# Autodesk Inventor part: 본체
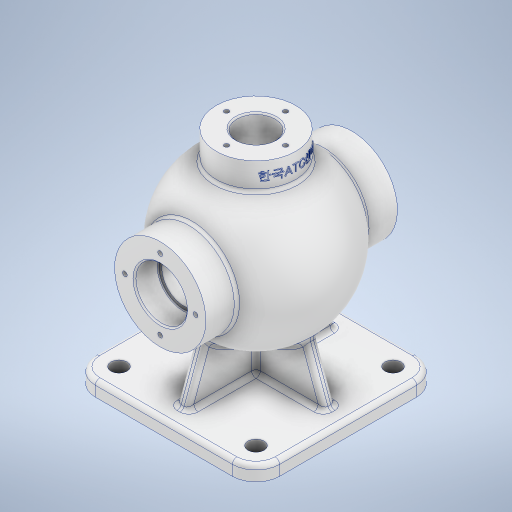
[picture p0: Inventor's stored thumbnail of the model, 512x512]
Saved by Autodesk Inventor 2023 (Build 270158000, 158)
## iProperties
Created: 2023-07
Part Number: 본체
Material: 알루미늄 6061
Document SubType Name: Modeling
Designer: Owner
Density: 2.7 g/cm^3
Appearance: 알루미늄 - 평지
Mass: 1526.65 g
Surface Area: 1174.15 cm^2
Volume: 565.427 cm^3
Author: Owner
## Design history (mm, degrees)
sketch "스케치3"
  geometry: L1 (-62.5, -62.5)-(62.5, -62.5); L2 (62.5, -62.5)-(62.5, 62.5); L3 (62.5, 62.5)-(-62.5, 62.5); L4 (-62.5, 62.5)-(-62.5, -62.5); L5 (-62.5, -62.5)-(62.5, 62.5); L6 (62.5, -62.5)-(-62.5, 62.5); 1 further point
  constraints: 12 end point, 2 midpoint, 2 parallel, 2 perpendicular, 1 horizontal
  dimensions: "d3" = 125 distance of L1.end L2.end
extrude "돌출1" new body sketch "스케치3" distance "d4" = 10; taper "d5" = 0 deg
sketch "스케치6"
  geometry: L1 (0, 62.5)-(0, -62.5) reference; L2 (85, 65)-(54, 65); L3 (54, -65)-(85, -65); L4 (85, -65)-(85, 65); L5 (85, 65)-(85, 54); L6 (85, -54)-(85, -65); L7 (54, 65)-(54, 44.215); L8 (54, -44.215)-(54, -65); L9 (85, 54)-(85, -54); A1 r 54 centre (85, 0) between (85, 54) and (85, -54); 8 further points
  constraints: 16 end point, 7 midpoint, 4 point on circle, 3 collinear, 3 parallel, 2 horizontal alignment, 2 perpendicular, 2 point on line, 1 centre point, 1 coincident, 1 horizontal
  dimensions: "d11" = 85 distance of point (0, 0) A1.centre; "d13" = 108 diameter of A1; "d14" = 130 distance of L2.end L3.start; "d15" = 31 distance from line of point (85, -59.5) L8; "d16" = 65 vertical distance of point (0, 0) point (69.5, 65)
revolve "회전2" sketch "스케치6" stored, may be unused: angle "d17" = 90 deg
sketch "스케치7"
  geometry: L1 (-62.5, 10)-(62.5, 10) reference; L2 (-50.5, 10)-(-23.202, 85); L3 (-62.5, 0)-(-62.5, 10) reference; L4 (62.5, 10)-(-62.5, 10) reference; L5 (50.5, 10)-(23.202, 85); L6 (62.5, 0)-(62.5, 10) reference; L7 (-23.202, 85)-(23.202, 85); L8 (62.5, 0)-(-62.5, 0) reference; C1 r 54 at (0, 85) reference; 5 further points
  constraints: 6 end point, 2 point on line, 1 horizontal, 1 midpoint
  dimensions: "d18" = 12 distance of L2.start L1.start; "d19" = 20 deg angle of L3 L2; "d20" = 12 distance of L1.end L5.start; "d22" = 20 deg angle of L6 L5; "d35" = 85 distance between parallel lines of L8 L7
extrude "돌출2" join sketch "스케치7" stored distance "d23" = 8; taper "d24" = 0 deg
sketch "스케치8"
  geometry: L1 (49.129, 36.258)-(10, 50.5); L2 (10, 62.5)-(10, -62.5) reference; L3 (0, 62.5)-(10, 62.5) reference; 1 further point
  constraints: 2 end point, 1 point on line
  dimensions: "d25" = 12 distance from line of L3 L1.end; "d26" = 20 deg angle of L3 L1
feature "리브2" sketch "스케치8" dims "d36" = 1, "d37" = 8, "d38" = 0, "d39" = 0, "d40" = 1, "d41" = 1
sketch "스케치9"
  geometry: C1 r 31 at (0, 0) reference; 2 further points
  constraints: 1 coincident
hole "구멍1" sketch "스케치9" at (0, 0) diameter "d42" = 30; stored, may be unused: countersink angle "d46" = 90 deg, drill point angle "d48" = 118 deg; dims "d43" = 4.4, "d44" = 35, "d45" = 16, "d47" = 7
sketch "스케치10"
  geometry: C1 r 31 at (0, 0) reference; 2 further points
  constraints: 1 coincident
hole "구멍2" sketch "스케치10" at (0, 0) diameter "d49" = 30; stored, may be unused: countersink angle "d53" = 90 deg, drill point angle "d55" = 118 deg; dims "d50" = 6, "d51" = 35, "d52" = 16, "d54" = 8
node "작업 평면1"
sketch "스케치11"
  geometry: C1 r 27 at (0, 0); 1 further point
  constraints: 1 centre point, 1 coincident
  dimensions: "d57" = 54 diameter of C1
extrude "돌출3" join sketch "스케치11" stored distance "d58" = 8; taper "d59" = 0 deg
sketch "스케치12"
  geometry: L1 (85, 44)-(85, -44); A1 r 54 centre (85, 0) between (46.034, -37.385) and (46.034, 37.385) reference; A2 r 44 centre (85, 0) between (85, -44) and (85, 44); 2 further points
  constraints: 2 coincident, 2 end point, 2 point on circle, 1 centre point, 1 midpoint, 1 vertical
  dimensions: "d60" = 88 diameter of A2
revolve "회전3" sketch "스케치12" stored, may be unused: angle "d61" = 90 deg
sketch "스케치13"
  geometry: C1 r 27 at (0, 0) reference; 2 further points
  constraints: 1 coincident
hole "구멍3" sketch "스케치13" at (0, 0) diameter "d62" = 26; stored, may be unused: countersink angle "d66" = 90 deg, drill point angle "d68" = 118 deg; dims "d63" = 6, "d64" = 35, "d65" = 16, "d67" = 8
sketch "스케치14"
  geometry: C1 r 13 at (0, 0) reference; 1 further point
  constraints: 1 vertical alignment
  dimensions: "d69" = 20 distance of C1.centre point (0, 20)
hole "구멍4" sketch "스케치14" at (0, 20) diameter "d70" = 3.242; stored, may be unused: countersink angle "d74" = 90 deg, drill point angle "d76" = 118 deg; dims "d71" = 9, "d72" = 4, "d73" = 2, "d75" = 11
sketch "스케치15"
  geometry: C1 r 17.5 at (0, 0) reference; 2 further points
  constraints: 1 vertical alignment
  dimensions: "d80" = 24 distance of C1.centre point (0, 24)
hole "구멍5" sketch "스케치15" at (0, 24) diameter "d81" = 3.242; stored, may be unused: countersink angle "d85" = 90 deg, drill point angle "d87" = 118 deg; dims "d82" = 12, "d83" = 4, "d84" = 2, "d86" = 15
fillet "모깎기3" dims "d91" = 16
fillet "모깎기4" dims "d92" = 3
fillet "모깎기5" dims "d93" = 3
fillet "모깎기6" dims "d94" = 3
chamfer "모따기1" distance "d95" = 1; stored, may be unused: second distance "d96" = 2, angle "d97" = 45 deg
fillet "모깎기7" dims "d98" = 0.6
sketch "스케치16"
  geometry: C1 r 5.5 at (-46.5, -46.5); A1 r 16 centre (-46.5, -46.5) between (-62.5, -46.5) and (-46.5, -62.5) reference; 1 further point
  constraints: 1 centre point, 1 coincident
  dimensions: "d99" = 11 diameter of C1
extrude "돌출4" cut sketch "스케치16" extent not by distance; stored distance "d100" = 10; taper "d101" = 0 deg
fillet "모깎기8" dims "d102" = 3
node "작업 평면2"
sketch "스케치17"
  geometry: L1 (0, -27)-(0, 27) reference; L2 (-150, 46.5)-(-150, -46.5) reference; 3 further points
  constraints: 1 horizontal alignment, 1 midpoint, 1 other
  dimensions: "d106" = 9 distance from line of L1 point (-9, 0)
feature "엠보싱1" sketch "스케치17" dims "d3" = 125, "d103" = 0.5, "d104" = 0
fillet "모깎기9" dims "d105" = 3
feature "̙耀̛耀̝耀̟耀̡耀̣耀̥耀̧耀" dims "d3" = 125, "d4" = 10, "d5" = 0, "d11" = 85, "d12" = 31, "d13" = 108, "d14" = 130, "d15" = 31, "d16" = 65, "d17" = 90 deg, "d18" = 12, "d19" = 20 deg, "d20" = 12, "d22" = 20 deg, "d23" = 8, "d24" = 0, "d25" = 12, "d26" = 20 deg, "d35" = 85, "d36" = 1, "d37" = 8, "d38" = 0, "d39" = 0, "d40" = 1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
node "솔리드2"
mirror "미러2"
pattern_circular "원형 패턴1" dims angle "d78" = 360 deg
pattern_circular "원형 패턴2" dims angle "d89" = 360 deg
mirror "미러3"
mirror "미러4"
mirror "미러5"
feature "A9D066F2-1C7D-4E18-AEED-F7BC21143FA4" dims "d42" = 30, "d43" = 4.4, "d44" = 35, "d45" = 16, "d46" = 90 deg, "d47" = 7, "d48" = 118 deg
